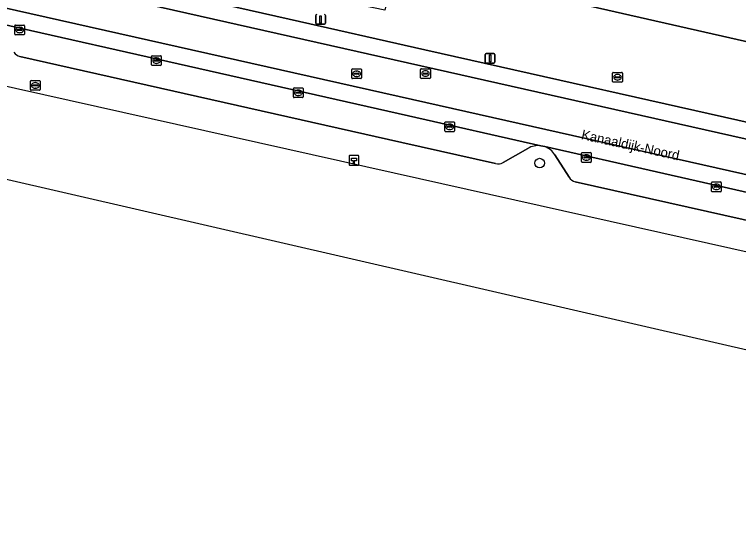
# Model space of a CAD drawing. Extents: x 162172 to 163187, y 382874 to 383685.
# Drawn here: x 162745.1 to 162819.5, y 382926.1 to 382978.9 of the extents above; entities that cross this region are included whole.
import ezdxf

# ---------------------------------------------------------------- set-up
doc = ezdxf.new("R2010")
doc.units = 0
for name, color, linetype in [('IMGEO_Berm_groen', 7, 'Continuous'), ('IMGEO_Boom', 7, 'Continuous'), ('IMGEO_Brandkraan', 7, 'Continuous'), ('IMGEO_Hectometerpaal', 7, 'Continuous'), ('IMGEO_Kolk', 7, 'Continuous'), ('IMGEO_Lichtmast', 7, 'Continuous'), ('IMGEO_Openbare_ruimte_label', 7, 'Continuous'), ('IMGEO_Pand', 7, 'Continuous'), ('IMGEO_Parkeervlak_open', 7, 'Continuous'), ('IMGEO_Rijbaan_lokaal_gesloten', 7, 'Continuous'), ('IMGEO_Rioolput', 7, 'Continuous'), ('IMGEO_Voetpad_open', 7, 'Continuous'), ('IMGEO_Waterloop', 7, 'Continuous')]:
    doc.layers.add(name, color=color, linetype=linetype)

msp = doc.modelspace()

# ---------------------------------------------------------------- linework, layer by layer
at = {"layer": 'IMGEO_Berm_groen'}
for points in [[(162720.216, 382976.882), (162784.129, 382962.6), (162870.915, 382943.206), (162909.146, 382934.598), (162909.41, 382935.821), (162910.726, 382935.534), (162910.508, 382934.291), (162914.803, 382933.324), (162915.225, 382935.32), (162915.367, 382935.288), (162916.011, 382938.149)], [(162794.556, 382963.557), (162784.911, 382965.727), (162745.684, 382974.551)], [(162799.607, 382965.303), (162799.197, 382965.389)], [(162797.863, 382965.113), (162795.324, 382963.67)], [(162802.111, 382962.156), (162800.64, 382964.465)], [(162909.937, 382937.607), (162821.972, 382957.364), (162802.742, 382961.697)]]:
    msp.add_lwpolyline(points, dxfattribs=at)
for centre, radius, start, end in [((162745.994, 382975.68), 1.171, 216.35786, 254.64815), ((162798.933, 382963.303), 2.103, 82.79144, 120.5873), ((162798.882, 382963.353), 2.081, 32.30734, 69.5927), ((162794.809, 382964.501), 0.977, 254.96415, 301.77621), ((162803.012, 382962.732), 1.069, 212.57084, 255.36362)]:
    msp.add_arc(centre, radius, start, end, dxfattribs=at)
at = {"layer": 'IMGEO_Boom'}
msp.add_circle((162799.084, 382963.615), 0.489, dxfattribs=at)
at = {"layer": 'IMGEO_Brandkraan'}
for p, q in [((162806.578, 382971.993), (162806.578, 382972.845)), ((162806.653, 382972.919), (162807.505, 382972.919)), ((162807.579, 382972.845), (162807.579, 382971.993)), ((162806.837, 382972.413), (162806.837, 382972.425)), ((162807.275, 382972.376), (162806.877, 382972.376)), ((162806.88, 382972.462), (162807.278, 382972.462)), ((162807.089, 382972.139), (162807.064, 382972.139)), ((162807.066, 382972.699), (162807.091, 382972.699)), ((162807.321, 382972.425), (162807.321, 382972.413)), ((162807.505, 382971.919), (162806.653, 382971.919))]:
    msp.add_line(p, q, dxfattribs=at)
for points in [[(162806.578, 382971.993), (162806.578, 382972.845)], [(162806.653, 382972.919), (162807.505, 382972.919)], [(162807.579, 382972.845), (162807.579, 382971.993)], [(162807.505, 382971.919), (162806.653, 382971.919)]]:
    msp.add_lwpolyline(points, dxfattribs=at)
for centre, radius, start, end in [((162806.655, 382972.843), 0.0765, 91.55205, 178.44795), ((162806.655, 382972.843), 0.0765, 91.55205, 178.44795), ((162807.503, 382972.843), 0.0765, 1.55205, 88.44795), ((162807.503, 382972.843), 0.0765, 1.55205, 88.44795), ((162806.655, 382971.995), 0.0765, 181.55205, 268.44795), ((162806.655, 382971.995), 0.0765, 181.55205, 268.44795), ((162806.877, 382972.422), 0.0403, 85.87752, 175.75265), ((162806.874, 382972.412), 0.0366, 178.93798, 274.71019), ((162807.278, 382972.419), 0.043, 264.86636, 352.45326), ((162807.282, 382972.424), 0.0386, 1.73085, 96.63898), ((162807.503, 382971.995), 0.0765, 271.55205, 358.44795), ((162807.503, 382971.995), 0.0765, 271.55205, 358.44795)]:
    msp.add_arc(centre, radius, start, end, dxfattribs=at)
for centre, major_axis, ratio, start_param, end_param in [((162807.065, 382972.419), (-0.387, 0.002), 0.722429, 4.712389, 7.853982), ((162807.09, 382972.419), (-0.39, 0.002), 0.717154, 1.570796, 4.712389)]:
    msp.add_ellipse(centre, major_axis=major_axis, ratio=ratio, start_param=start_param, end_param=end_param, dxfattribs=at)
at = {"layer": 'IMGEO_Hectometerpaal'}
for p, q in [((162779.506, 382964.304), (162779.506, 382963.463)), ((162779.506, 382964.304), (162779.506, 382963.463)), ((162780.422, 382964.388), (162779.581, 382964.388)), ((162780.422, 382964.388), (162779.581, 382964.388)), ((162780.506, 382963.472), (162780.506, 382964.313)), ((162780.506, 382963.472), (162780.506, 382964.313)), ((162779.59, 382963.388), (162780.431, 382963.388)), ((162779.59, 382963.388), (162780.431, 382963.388))]:
    msp.add_line(p, q, dxfattribs=at)
msp.add_lwpolyline([(162780.031, 382963.532), (162779.971, 382963.532), (162779.971, 382963.837), (162779.751, 382963.837), (162779.751, 382964.106), (162780.251, 382964.106), (162780.251, 382963.837), (162780.031, 382963.837), (162780.031, 382963.532)], dxfattribs=at)
for centre, start, end in [((162779.584, 382964.31), 92.4484, 184.28452), ((162779.584, 382964.31), 92.4484, 184.28452), ((162780.428, 382964.31), 2.4484, 94.28452), ((162780.428, 382964.31), 2.4484, 94.28452), ((162779.584, 382963.466), 182.4484, 274.28452), ((162779.584, 382963.466), 182.4484, 274.28452), ((162780.428, 382963.466), 272.4484, 4.28452), ((162780.428, 382963.466), 272.4484, 4.28452)]:
    msp.add_arc(centre, 0.0779, start, end, dxfattribs=at)
at = {"layer": 'IMGEO_Kolk'}
for p, q in [((162745.144, 382976.848), (162745.144, 382977.7)), ((162745.219, 382977.774), (162746.071, 382977.774)), ((162745.403, 382977.268), (162745.403, 382977.28)), ((162745.841, 382977.231), (162745.443, 382977.231)), ((162745.446, 382977.317), (162745.844, 382977.317)), ((162745.632, 382977.554), (162745.657, 382977.554)), ((162745.887, 382977.28), (162745.887, 382977.268)), ((162746.145, 382977.7), (162746.145, 382976.848)), ((162746.071, 382976.774), (162745.219, 382976.774)), ((162745.655, 382976.994), (162745.63, 382976.994)), ((162759.208, 382973.703), (162759.208, 382974.555)), ((162759.283, 382974.629), (162760.135, 382974.629)), ((162759.696, 382974.409), (162759.721, 382974.409)), ((162760.209, 382974.555), (162760.209, 382973.703)), ((162760.135, 382973.629), (162759.283, 382973.629)), ((162759.467, 382974.123), (162759.467, 382974.135)), ((162759.905, 382974.086), (162759.507, 382974.086)), ((162759.51, 382974.172), (162759.908, 382974.172)), ((162759.719, 382973.849), (162759.694, 382973.849)), ((162759.951, 382974.135), (162759.951, 382974.123)), ((162746.758, 382971.162), (162746.758, 382972.014)), ((162746.833, 382972.088), (162747.685, 382972.088)), ((162747.759, 382972.014), (162747.759, 382971.162)), ((162747.017, 382971.582), (162747.017, 382971.594)), ((162747.455, 382971.545), (162747.057, 382971.545)), ((162747.06, 382971.631), (162747.458, 382971.631)), ((162747.269, 382971.308), (162747.244, 382971.308)), ((162747.246, 382971.868), (162747.271, 382971.868)), ((162747.501, 382971.594), (162747.501, 382971.582)), ((162773.777, 382970.406), (162773.777, 382971.258)), ((162773.852, 382971.332), (162774.704, 382971.332)), ((162774.778, 382971.258), (162774.778, 382970.406)), ((162747.685, 382971.088), (162746.833, 382971.088)), ((162774.036, 382970.826), (162774.036, 382970.838)), ((162774.474, 382970.789), (162774.076, 382970.789)), ((162774.079, 382970.875), (162774.477, 382970.875)), ((162774.288, 382970.552), (162774.263, 382970.552)), ((162774.265, 382971.112), (162774.29, 382971.112)), ((162774.52, 382970.838), (162774.52, 382970.826)), ((162774.704, 382970.332), (162773.852, 382970.332)), ((162789.337, 382966.912), (162789.337, 382967.764)), ((162789.412, 382967.838), (162790.264, 382967.838)), ((162789.825, 382967.618), (162789.85, 382967.618)), ((162790.338, 382967.764), (162790.338, 382966.912)), ((162790.264, 382966.838), (162789.412, 382966.838)), ((162789.596, 382967.332), (162789.596, 382967.344)), ((162790.034, 382967.295), (162789.636, 382967.295)), ((162789.639, 382967.381), (162790.037, 382967.381)), ((162789.848, 382967.058), (162789.823, 382967.058)), ((162790.08, 382967.344), (162790.08, 382967.332)), ((162803.382, 382963.764), (162803.382, 382964.616)), ((162803.457, 382964.69), (162804.309, 382964.69)), ((162804.383, 382964.616), (162804.383, 382963.764)), ((162803.641, 382964.184), (162803.641, 382964.196)), ((162804.079, 382964.147), (162803.681, 382964.147)), ((162803.684, 382964.233), (162804.082, 382964.233)), ((162803.893, 382963.91), (162803.868, 382963.91)), ((162803.87, 382964.47), (162803.895, 382964.47)), ((162804.125, 382964.196), (162804.125, 382964.184)), ((162804.309, 382963.69), (162803.457, 382963.69)), ((162816.74, 382960.748), (162816.74, 382961.6)), ((162816.815, 382961.674), (162817.667, 382961.674)), ((162817.741, 382961.6), (162817.741, 382960.748)), ((162816.999, 382961.168), (162816.999, 382961.18)), ((162817.437, 382961.131), (162817.039, 382961.131)), ((162817.042, 382961.217), (162817.44, 382961.217)), ((162817.251, 382960.894), (162817.226, 382960.894)), ((162817.228, 382961.454), (162817.253, 382961.454)), ((162817.483, 382961.18), (162817.483, 382961.168)), ((162817.667, 382960.674), (162816.815, 382960.674))]:
    msp.add_line(p, q, dxfattribs=at)
for points in [[(162745.144, 382976.848), (162745.144, 382977.7)], [(162745.219, 382977.774), (162746.071, 382977.774)], [(162746.145, 382977.7), (162746.145, 382976.848)], [(162746.071, 382976.774), (162745.219, 382976.774)], [(162759.208, 382973.703), (162759.208, 382974.555)], [(162759.283, 382974.629), (162760.135, 382974.629)], [(162760.209, 382974.555), (162760.209, 382973.703)], [(162760.135, 382973.629), (162759.283, 382973.629)], [(162746.758, 382971.162), (162746.758, 382972.014)], [(162746.833, 382972.088), (162747.685, 382972.088)], [(162747.759, 382972.014), (162747.759, 382971.162)], [(162773.777, 382970.406), (162773.777, 382971.258)], [(162773.852, 382971.332), (162774.704, 382971.332)], [(162774.778, 382971.258), (162774.778, 382970.406)], [(162747.685, 382971.088), (162746.833, 382971.088)], [(162774.704, 382970.332), (162773.852, 382970.332)], [(162789.337, 382966.912), (162789.337, 382967.764)], [(162789.412, 382967.838), (162790.264, 382967.838)], [(162790.338, 382967.764), (162790.338, 382966.912)], [(162790.264, 382966.838), (162789.412, 382966.838)], [(162803.382, 382963.764), (162803.382, 382964.616)], [(162803.457, 382964.69), (162804.309, 382964.69)], [(162804.383, 382964.616), (162804.383, 382963.764)], [(162804.309, 382963.69), (162803.457, 382963.69)], [(162816.74, 382960.748), (162816.74, 382961.6)], [(162816.815, 382961.674), (162817.667, 382961.674)], [(162817.741, 382961.6), (162817.741, 382960.748)], [(162817.667, 382960.674), (162816.815, 382960.674)]]:
    msp.add_lwpolyline(points, dxfattribs=at)
for centre, radius, start, end in [((162745.221, 382977.698), 0.0765, 91.55205, 178.44795), ((162745.221, 382977.698), 0.0765, 91.55205, 178.44795), ((162745.443, 382977.277), 0.0403, 85.87752, 175.75265), ((162745.44, 382977.267), 0.0366, 178.93798, 274.71019), ((162745.844, 382977.274), 0.043, 264.86636, 352.45326), ((162745.848, 382977.279), 0.0386, 1.73085, 96.63898), ((162746.069, 382977.698), 0.0765, 1.55205, 88.44795), ((162746.069, 382977.698), 0.0765, 1.55205, 88.44795), ((162745.221, 382976.85), 0.0765, 181.55205, 268.44795), ((162745.221, 382976.85), 0.0765, 181.55205, 268.44795), ((162746.069, 382976.85), 0.0765, 271.55205, 358.44795), ((162746.069, 382976.85), 0.0765, 271.55205, 358.44795), ((162759.285, 382974.553), 0.0765, 91.55205, 178.44795), ((162759.285, 382974.553), 0.0765, 91.55205, 178.44795), ((162760.133, 382974.553), 0.0765, 1.55205, 88.44795), ((162760.133, 382974.553), 0.0765, 1.55205, 88.44795), ((162759.285, 382973.705), 0.0765, 181.55205, 268.44795), ((162759.285, 382973.705), 0.0765, 181.55205, 268.44795), ((162759.507, 382974.132), 0.0403, 85.87752, 175.75265), ((162759.504, 382974.122), 0.0366, 178.93798, 274.71019), ((162759.908, 382974.129), 0.043, 264.86636, 352.45326), ((162759.912, 382974.134), 0.0386, 1.73085, 96.63898), ((162760.133, 382973.705), 0.0765, 271.55205, 358.44795), ((162760.133, 382973.705), 0.0765, 271.55205, 358.44795), ((162746.835, 382972.012), 0.0765, 91.55205, 178.44795), ((162746.835, 382972.012), 0.0765, 91.55205, 178.44795), ((162747.683, 382972.012), 0.0765, 1.55205, 88.44795), ((162747.683, 382972.012), 0.0765, 1.55205, 88.44795), ((162747.057, 382971.591), 0.0403, 85.87752, 175.75265), ((162747.054, 382971.581), 0.0366, 178.93798, 274.71019), ((162747.458, 382971.588), 0.043, 264.86636, 352.45326), ((162747.462, 382971.593), 0.0386, 1.73085, 96.63898), ((162773.854, 382971.256), 0.0765, 91.55205, 178.44795), ((162773.854, 382971.256), 0.0765, 91.55205, 178.44795), ((162774.702, 382971.256), 0.0765, 1.55205, 88.44795), ((162774.702, 382971.256), 0.0765, 1.55205, 88.44795), ((162746.835, 382971.164), 0.0765, 181.55205, 268.44795), ((162746.835, 382971.164), 0.0765, 181.55205, 268.44795), ((162747.683, 382971.164), 0.0765, 271.55205, 358.44795), ((162747.683, 382971.164), 0.0765, 271.55205, 358.44795), ((162774.076, 382970.835), 0.0403, 85.87752, 175.75265), ((162774.073, 382970.825), 0.0366, 178.93798, 274.71019), ((162774.477, 382970.832), 0.043, 264.86636, 352.45326), ((162774.481, 382970.837), 0.0386, 1.73085, 96.63898), ((162773.854, 382970.408), 0.0765, 181.55205, 268.44795), ((162773.854, 382970.408), 0.0765, 181.55205, 268.44795), ((162774.702, 382970.408), 0.0765, 271.55205, 358.44795), ((162774.702, 382970.408), 0.0765, 271.55205, 358.44795), ((162789.414, 382967.762), 0.0765, 91.55205, 178.44795), ((162789.414, 382967.762), 0.0765, 91.55205, 178.44795), ((162790.262, 382967.762), 0.0765, 1.55205, 88.44795), ((162790.262, 382967.762), 0.0765, 1.55205, 88.44795), ((162789.414, 382966.914), 0.0765, 181.55205, 268.44795), ((162789.414, 382966.914), 0.0765, 181.55205, 268.44795), ((162789.636, 382967.341), 0.0403, 85.87752, 175.75265), ((162789.633, 382967.331), 0.0366, 178.93798, 274.71019), ((162790.037, 382967.338), 0.043, 264.86636, 352.45326), ((162790.041, 382967.343), 0.0386, 1.73085, 96.63898), ((162790.262, 382966.914), 0.0765, 271.55205, 358.44795), ((162790.262, 382966.914), 0.0765, 271.55205, 358.44795), ((162803.459, 382964.614), 0.0765, 91.55205, 178.44795), ((162803.459, 382964.614), 0.0765, 91.55205, 178.44795), ((162804.307, 382964.614), 0.0765, 1.55205, 88.44795), ((162804.307, 382964.614), 0.0765, 1.55205, 88.44795), ((162803.681, 382964.193), 0.0403, 85.87752, 175.75265), ((162803.678, 382964.183), 0.0366, 178.93798, 274.71019), ((162804.082, 382964.19), 0.043, 264.86636, 352.45326), ((162804.086, 382964.195), 0.0386, 1.73085, 96.63898), ((162803.459, 382963.766), 0.0765, 181.55205, 268.44795), ((162803.459, 382963.766), 0.0765, 181.55205, 268.44795), ((162804.307, 382963.766), 0.0765, 271.55205, 358.44795), ((162804.307, 382963.766), 0.0765, 271.55205, 358.44795), ((162816.817, 382961.598), 0.0765, 91.55205, 178.44795), ((162816.817, 382961.598), 0.0765, 91.55205, 178.44795), ((162817.665, 382961.598), 0.0765, 1.55205, 88.44795), ((162817.665, 382961.598), 0.0765, 1.55205, 88.44795), ((162817.039, 382961.177), 0.0403, 85.87752, 175.75265), ((162817.036, 382961.167), 0.0366, 178.93798, 274.71019), ((162817.44, 382961.174), 0.043, 264.86636, 352.45326), ((162817.444, 382961.179), 0.0386, 1.73085, 96.63898), ((162816.817, 382960.75), 0.0765, 181.55205, 268.44795), ((162816.817, 382960.75), 0.0765, 181.55205, 268.44795), ((162817.665, 382960.75), 0.0765, 271.55205, 358.44795), ((162817.665, 382960.75), 0.0765, 271.55205, 358.44795)]:
    msp.add_arc(centre, radius, start, end, dxfattribs=at)
for centre, major_axis, ratio, start_param, end_param in [((162745.631, 382977.274), (-0.387, 0.002), 0.722429, 4.712389, 7.853982), ((162745.656, 382977.274), (-0.39, 0.002), 0.717154, 1.570796, 4.712389), ((162759.695, 382974.129), (-0.387, 0.002), 0.722429, 4.712389, 7.853982), ((162759.72, 382974.129), (-0.39, 0.002), 0.717154, 1.570796, 4.712389), ((162747.245, 382971.588), (-0.387, 0.002), 0.722429, 4.712389, 7.853982), ((162747.27, 382971.588), (-0.39, 0.002), 0.717154, 1.570796, 4.712389), ((162774.264, 382970.832), (-0.387, 0.002), 0.722429, 4.712389, 7.853982), ((162774.289, 382970.832), (-0.39, 0.002), 0.717154, 1.570796, 4.712389), ((162789.824, 382967.338), (-0.387, 0.002), 0.722429, 4.712389, 7.853982), ((162789.849, 382967.338), (-0.39, 0.002), 0.717154, 1.570796, 4.712389), ((162803.869, 382964.19), (-0.387, 0.002), 0.722429, 4.712389, 7.853982), ((162803.894, 382964.19), (-0.39, 0.002), 0.717154, 1.570796, 4.712389), ((162817.227, 382961.174), (-0.387, 0.002), 0.722429, 4.712389, 7.853982), ((162817.252, 382961.174), (-0.39, 0.002), 0.717154, 1.570796, 4.712389)]:
    msp.add_ellipse(centre, major_axis=major_axis, ratio=ratio, start_param=start_param, end_param=end_param, dxfattribs=at)
at = {"layer": 'IMGEO_Lichtmast'}
for p, q in [((162776.072, 382977.964), (162776.072, 382978.764)), ((162776.072, 382978.764), (162776.072, 382977.964)), ((162777.062, 382978.764), (162777.062, 382977.964)), ((162777.062, 382977.964), (162777.062, 382978.764)), ((162776.962, 382977.864), (162776.172, 382977.864)), ((162776.172, 382977.864), (162776.962, 382977.864)), ((162793.494, 382973.965), (162793.494, 382974.765)), ((162793.494, 382974.765), (162793.494, 382973.965)), ((162793.594, 382974.865), (162794.384, 382974.865)), ((162794.384, 382974.865), (162793.594, 382974.865)), ((162794.484, 382974.765), (162794.484, 382973.965)), ((162794.484, 382973.965), (162794.484, 382974.765)), ((162794.384, 382973.865), (162793.594, 382973.865)), ((162793.594, 382973.865), (162794.384, 382973.865))]:
    msp.add_line(p, q, dxfattribs=at)
for points in [[(162776.492, 382978.739), (162776.642, 382978.739), (162776.642, 382977.989), (162776.492, 382977.989), (162776.492, 382978.739)], [(162793.914, 382974.74), (162794.064, 382974.74), (162794.064, 382973.99), (162793.914, 382973.99), (162793.914, 382974.74)]]:
    msp.add_lwpolyline(points, dxfattribs=at)
for centre, start, end in [((162776.172, 382978.764), 90, 180), ((162776.172, 382978.764), 90, 180), ((162776.962, 382978.764), 0, 90), ((162776.962, 382978.764), 360, 90), ((162776.172, 382977.964), 180, 270), ((162776.172, 382977.964), 180, 270), ((162776.962, 382977.964), 270, 0), ((162776.962, 382977.964), 270, 0), ((162793.594, 382974.765), 90, 180), ((162793.594, 382974.765), 90, 180), ((162794.384, 382974.765), 0, 90), ((162794.384, 382974.765), 360, 90), ((162793.594, 382973.965), 180, 270), ((162793.594, 382973.965), 180, 270), ((162794.384, 382973.965), 270, 0), ((162794.384, 382973.965), 270, 0)]:
    msp.add_arc(centre, 0.1, start, end, dxfattribs=at)
at = {"layer": 'IMGEO_Pand'}
msp.add_lwpolyline([(162824.109, 382985.314), (162825.229, 382990.27), (162816.058, 382992.342), (162815.169, 382988.41), (162813.304, 382988.831), (162812.024, 382986.851), (162806.173, 382988.174), (162805.364, 382984.594), (162804.261, 382979.717), (162821.941, 382975.721), (162823.043, 382980.599)], close=True, dxfattribs=at)
at = {"layer": 'IMGEO_Parkeervlak_open'}
for points in [[(162799.197, 382965.389), (162785.592, 382968.454), (162742.474, 382978.167)], [(162745.684, 382974.551), (162784.911, 382965.727), (162794.556, 382963.557)], [(162914.534, 382939.493), (162822.549, 382960.121), (162799.607, 382965.303)], [(162795.324, 382963.67), (162797.863, 382965.113)], [(162800.64, 382964.465), (162802.111, 382962.156)], [(162802.742, 382961.697), (162821.972, 382957.364), (162909.937, 382937.607)]]:
    msp.add_lwpolyline(points, dxfattribs=at)
for centre, radius, start, end in [((162745.994, 382975.68), 1.171, 216.35786, 254.64815), ((162798.933, 382963.303), 2.103, 82.79144, 120.5873), ((162798.882, 382963.353), 2.081, 32.30734, 69.5927), ((162794.809, 382964.501), 0.977, 254.96415, 301.77621), ((162803.012, 382962.732), 1.069, 212.57084, 255.36362)]:
    msp.add_arc(centre, radius, start, end, dxfattribs=at)
at = {"layer": 'IMGEO_Rijbaan_lokaal_gesloten'}
for points in [[(162829.302, 382965.805), (162824.157, 382966.963), (162787.291, 382975.248), (162773.34, 382978.384), (162571.899, 383023.687), (162571.522, 383022.029), (162786.88, 382973.603), (162917.14, 382944.312), (162943.106, 382938.499), (163087.202, 382906.239), (163087.933, 382911.374)], [(163083.281, 382900.241), (163086.245, 382899.688), (163087.202, 382906.239), (162943.106, 382938.499), (162917.14, 382944.312), (162786.88, 382973.603), (162571.522, 383022.029), (162570.463, 383017.371), (162571.857, 383017.418)], [(162582.55, 383015.84), (162786.012, 382970.134), (162942.339, 382935.016), (163063.468, 382907.805)], [(162786.012, 382970.134), (162582.55, 383015.84)], [(162578.735, 383014.966), (162579.914, 383014.696), (162633.717, 383002.605), (162634.011, 383002.544), (162686.729, 382990.692), (162687.058, 382990.622), (162702.086, 382987.23), (162742.081, 382978.256), (162742.474, 382978.167), (162785.592, 382968.454), (162799.197, 382965.389), (162799.607, 382965.303), (162822.549, 382960.121), (162914.534, 382939.493), (162915.372, 382939.293), (162941.966, 382933.318), (162958.833, 382929.528), (162973.588, 382926.269), (162974.816, 382925.987), (163061.72, 382906.535), (163062.776, 382906.254), (163065.631, 382905.242)], [(163063.468, 382907.805), (162942.339, 382935.016), (162786.012, 382970.134)]]:
    msp.add_lwpolyline(points, dxfattribs=at)
at = {"layer": 'IMGEO_Rioolput'}
for p, q in [((162779.774, 382972.358), (162779.774, 382973.21)), ((162779.849, 382973.284), (162780.701, 382973.284)), ((162780.033, 382972.778), (162780.033, 382972.79)), ((162780.471, 382972.741), (162780.073, 382972.741)), ((162780.076, 382972.827), (162780.474, 382972.827)), ((162780.262, 382973.064), (162780.287, 382973.064)), ((162780.517, 382972.79), (162780.517, 382972.778)), ((162780.775, 382973.21), (162780.775, 382972.358)), ((162786.853, 382972.372), (162786.853, 382973.224)), ((162786.928, 382973.298), (162787.78, 382973.298)), ((162787.112, 382972.792), (162787.112, 382972.804)), ((162787.55, 382972.755), (162787.152, 382972.755)), ((162787.155, 382972.841), (162787.553, 382972.841)), ((162787.341, 382973.078), (162787.366, 382973.078)), ((162787.596, 382972.804), (162787.596, 382972.792)), ((162787.854, 382973.224), (162787.854, 382972.372)), ((162780.701, 382972.284), (162779.849, 382972.284)), ((162780.285, 382972.504), (162780.26, 382972.504)), ((162787.78, 382972.298), (162786.928, 382972.298)), ((162787.364, 382972.518), (162787.339, 382972.518))]:
    msp.add_line(p, q, dxfattribs=at)
for points in [[(162779.774, 382972.358), (162779.774, 382973.21)], [(162779.849, 382973.284), (162780.701, 382973.284)], [(162780.775, 382973.21), (162780.775, 382972.358)], [(162786.853, 382972.372), (162786.853, 382973.224)], [(162786.928, 382973.298), (162787.78, 382973.298)], [(162787.854, 382973.224), (162787.854, 382972.372)], [(162780.701, 382972.284), (162779.849, 382972.284)], [(162787.78, 382972.298), (162786.928, 382972.298)]]:
    msp.add_lwpolyline(points, dxfattribs=at)
for centre, radius, start, end in [((162779.851, 382973.208), 0.0765, 91.55205, 178.44795), ((162779.851, 382973.208), 0.0765, 91.55205, 178.44795), ((162780.073, 382972.787), 0.0403, 85.87752, 175.75265), ((162780.07, 382972.777), 0.0366, 178.93798, 274.71019), ((162780.474, 382972.784), 0.043, 264.86636, 352.45326), ((162780.478, 382972.789), 0.0386, 1.73085, 96.63898), ((162780.699, 382973.208), 0.0765, 1.55205, 88.44795), ((162780.699, 382973.208), 0.0765, 1.55205, 88.44795), ((162786.93, 382973.222), 0.0765, 91.55205, 178.44795), ((162786.93, 382973.222), 0.0765, 91.55205, 178.44795), ((162787.152, 382972.801), 0.0403, 85.87752, 175.75265), ((162787.149, 382972.791), 0.0366, 178.93798, 274.71019), ((162787.553, 382972.798), 0.043, 264.86636, 352.45326), ((162787.557, 382972.803), 0.0386, 1.73085, 96.63898), ((162787.778, 382973.222), 0.0765, 1.55205, 88.44795), ((162787.778, 382973.222), 0.0765, 1.55205, 88.44795), ((162779.851, 382972.36), 0.0765, 181.55205, 268.44795), ((162779.851, 382972.36), 0.0765, 181.55205, 268.44795), ((162780.699, 382972.36), 0.0765, 271.55205, 358.44795), ((162780.699, 382972.36), 0.0765, 271.55205, 358.44795), ((162786.93, 382972.374), 0.0765, 181.55205, 268.44795), ((162786.93, 382972.374), 0.0765, 181.55205, 268.44795), ((162787.778, 382972.374), 0.0765, 271.55205, 358.44795), ((162787.778, 382972.374), 0.0765, 271.55205, 358.44795)]:
    msp.add_arc(centre, radius, start, end, dxfattribs=at)
for centre, major_axis, ratio, start_param, end_param in [((162780.261, 382972.784), (-0.387, 0.002), 0.722429, 4.712389, 7.853982), ((162780.286, 382972.784), (-0.39, 0.002), 0.717154, 1.570796, 4.712389), ((162787.34, 382972.798), (-0.387, 0.002), 0.722429, 4.712389, 7.853982), ((162787.365, 382972.798), (-0.39, 0.002), 0.717154, 1.570796, 4.712389)]:
    msp.add_ellipse(centre, major_axis=major_axis, ratio=ratio, start_param=start_param, end_param=end_param, dxfattribs=at)
at = {"layer": 'IMGEO_Voetpad_open'}
for points in [[(162571.899, 383023.687), (162773.34, 382978.384), (162787.291, 382975.248), (162824.157, 382966.963), (162829.302, 382965.805), (162943.475, 382940.176)], [(162821.941, 382975.721), (162804.261, 382979.717), (162784.276, 382984.222), (162783.727, 382981.735), (162783.188, 382979.294), (162780.843, 382979.797), (162781.397, 382982.297), (162781.94, 382984.748), (162778.845, 382985.446), (162777.762, 382980.49), (162776.092, 382980.864), (162772.065, 382981.765), (162773.202, 382986.741), (162765.246, 382988.58), (162764.083, 382983.586), (162758.708, 382984.776), (162757.377, 382985.098), (162751.675, 382986.375), (162752.431, 382989.644), (162752.848, 382991.445), (162753.316, 382993.468), (162728.656, 382999.416)]]:
    msp.add_lwpolyline(points, dxfattribs=at)
at = {"layer": 'IMGEO_Waterloop'}
for points in [[(163125.436, 382874.202), (162549.091, 383006.865), (162500.065, 383018.15)], [(162720.216, 382976.882), (162784.129, 382962.6), (162870.915, 382943.206), (162909.146, 382934.598), (162910.508, 382934.291), (162914.803, 382933.324), (162924.84, 382931.065), (162926.207, 382930.757), (162940.685, 382927.497)]]:
    msp.add_lwpolyline(points, dxfattribs=at)

# ---------------------------------------------------------------- texts
at = {"layer": 'IMGEO_Openbare_ruimte_label'}
msp.add_text('Kanaaldijk-Noord', height=1, rotation=347.58923, dxfattribs=at).set_placement((162803.3, 382966.084))
msp.add_text('Kanaaldijk-Noord', height=1, rotation=347.58923, dxfattribs=at).set_placement((162803.3, 382966.084))

doc.saveas('drawing.dxf')
